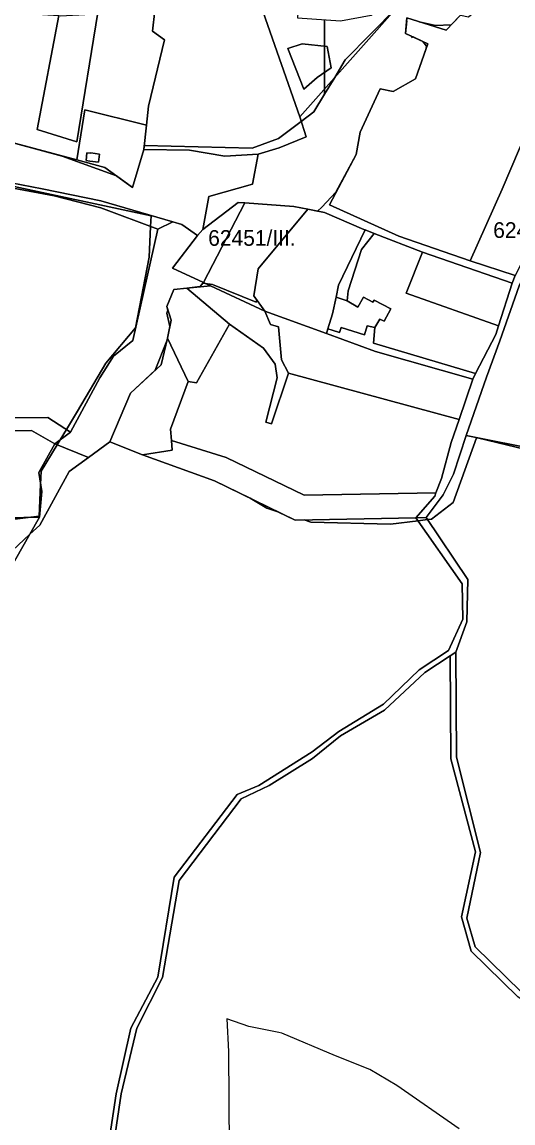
# Model space of a CAD drawing. Extents: x -502026 to -497664, y -1143484 to -1138019.
# Drawn here: x -498840 to -498590, y -1142180 to -1141619 of the extents above; entities that cross this region are included whole.
import ezdxf

# ---------------------------------------------------------------- set-up
doc = ezdxf.new("R2010")
doc.units = 0
for name, color, linetype in [('25', 7, 'Continuous'), ('31', 7, 'Continuous'), ('37', 7, 'Continuous'), ('43', 7, 'Continuous'), ('55', 7, 'Continuous'), ('62', 7, 'Continuous'), ('7', 7, 'Continuous')]:
    doc.layers.add(name, color=color, linetype=linetype)

msp = doc.modelspace()

# ---------------------------------------------------------------- linework, layer by layer
at = {"layer": '25'}
for points in [[(-498821.5, -1141615.93), (-498820.61, -1141616.01), (-498808.23, -1141615.35), (-498801.68, -1141614.26), (-498812.29, -1141680.22), (-498832.5, -1141673.92)], [(-498776.89, -1141671.76), (-498778.26, -1141684.08), (-498783.98, -1141703.56), (-498798.11, -1141693.25), (-498812.44, -1141689.43), (-498808.21, -1141663.92)], [(-498807.18, -1141685.78), (-498807.65, -1141689.81), (-498805.75, -1141690.03), (-498801.27, -1141690.56), (-498800.78, -1141686.44), (-498805.26, -1141685.9), (-498805.28, -1141686.01)], [(-498636.1, -1141736.52), (-498644.49, -1141757.44), (-498597.3, -1141774.04), (-498598.75, -1141778.37), (-498609.16, -1141798.36), (-498661.05, -1141782.91), (-498660.37, -1141774.86), (-498657.78, -1141770.53), (-498655.63, -1141771.68), (-498652.28, -1141765.42), (-498660.83, -1141760.84), (-498661.42, -1141761.94), (-498666.27, -1141759.35), (-498669.03, -1141764.51), (-498674.5, -1141761.18), (-498673.99, -1141756.14), (-498667.24, -1141735.13), (-498660.67, -1141726.97)], [(-498590.32, -1141752.32), (-498597.3, -1141774.04), (-498644.49, -1141757.44), (-498636.1, -1141736.52)]]:
    msp.add_lwpolyline(points, close=True, dxfattribs=at)
at = {"layer": '31'}
for points in [[(-498821.5, -1141615.93), (-498832.5, -1141673.92), (-498812.29, -1141680.22), (-498801.68, -1141614.26), (-498787.15, -1141613), (-498772.57, -1141613.25), (-498773.73, -1141623.84), (-498767.62, -1141628.33), (-498775.76, -1141662.06), (-498776.89, -1141671.76), (-498808.21, -1141663.92), (-498812.44, -1141689.43), (-498855.78, -1141677.89), (-498846.98, -1141615.47), (-498843.3, -1141602.91), (-498844.02, -1141614.47)], [(-498555.48, -1141734.78), (-498529.35, -1141741.87), (-498525.92, -1141742.8), (-498522.72, -1141754.01), (-498546.95, -1141790.01), (-498556.66, -1141818.24), (-498566.28, -1141830.25), (-498575.47, -1141837.59), (-498613.88, -1141829.95), (-498603.5, -1141800.08), (-498596.59, -1141781.61), (-498586.82, -1141753.62), (-498582.48, -1141744.58), (-498574.93, -1141729.51)]]:
    msp.add_lwpolyline(points, close=True, dxfattribs=at)
at = {"layer": '37'}
for points in [[(-498557.86, -1141620.31), (-498579.16, -1141667.75), (-498586.65, -1141683.62), (-498595.46, -1141704.28), (-498611.77, -1141740.81), (-498648.14, -1141728.24), (-498683.59, -1141712.28), (-498669.98, -1141686.66), (-498667.93, -1141675.26), (-498657.61, -1141653.21), (-498650.99, -1141654.52), (-498639.74, -1141648.11), (-498633.36, -1141630.35), (-498644.79, -1141624.98), (-498644.02, -1141617.12), (-498624.09, -1141623.37), (-498616.79, -1141615.76), (-498612.61, -1141616.54), (-498606.51, -1141611.58), (-498603.56, -1141602.08), (-498594.48, -1141602.56), (-498583.73, -1141606.31), (-498572.2, -1141605.96), (-498562.32, -1141613.57)], [(-498542.66, -1141654.6), (-498556.29, -1141686.3), (-498560.31, -1141693.56), (-498569.25, -1141709.41), (-498588.89, -1141748.42), (-498611.77, -1141740.81), (-498595.46, -1141704.28), (-498586.65, -1141683.62), (-498579.16, -1141667.75), (-498557.86, -1141620.31)], [(-498726.76, -1141711.34), (-498747.75, -1141751.96), (-498763.66, -1141744.65), (-498750.89, -1141728.01), (-498748.15, -1141724.96), (-498730.12, -1141711.09)], [(-498665.4, -1141725.13), (-498678.88, -1141753.3), (-498680.17, -1141759.36), (-498681.96, -1141767.81), (-498684.38, -1141775.59), (-498685.13, -1141777.99), (-498716.52, -1141766.51), (-498722.08, -1141758.73), (-498719.97, -1141744.88), (-498694.58, -1141714.57), (-498686.08, -1141716.19), (-498665.95, -1141724.92)], [(-498734.57, -1141773.1), (-498751.34, -1141803.01), (-498755.67, -1141802.36), (-498766.21, -1141780.37), (-498764.25, -1141771.04), (-498766.51, -1141764.17), (-498762.82, -1141755.42), (-498756.25, -1141754.78)], [(-498716.52, -1141766.51), (-498713.53, -1141773.24), (-498709.48, -1141774.43), (-498708.04, -1141791.33), (-498704.49, -1141798.18), (-498713.07, -1141823.97), (-498716.02, -1141823.16), (-498710.18, -1141800.46), (-498711.22, -1141793.46), (-498717.15, -1141785.3), (-498734.57, -1141773.1), (-498756.25, -1141754.78), (-498744.19, -1141753.6)], [(-498685.13, -1141777.99), (-498660.07, -1141787.08), (-498610.42, -1141801.16), (-498617.46, -1141821.72), (-498704.49, -1141798.18), (-498708.04, -1141791.33), (-498709.48, -1141774.43), (-498713.53, -1141773.24), (-498716.52, -1141766.51)], [(-498704.49, -1141798.18), (-498617.46, -1141821.72), (-498621.45, -1141833.38), (-498626.36, -1141851.84), (-498629.29, -1141859.04), (-498696.42, -1141860.25), (-498736.25, -1141841.02), (-498764.16, -1141832.39), (-498764.66, -1141826.73), (-498755.67, -1141802.36), (-498751.34, -1141803.01), (-498734.57, -1141773.1), (-498717.15, -1141785.3), (-498711.22, -1141793.46), (-498710.18, -1141800.46), (-498716.02, -1141823.16), (-498713.07, -1141823.97)], [(-498755.67, -1141802.36), (-498764.66, -1141826.73), (-498764.16, -1141832.39), (-498763.71, -1141837.32), (-498778.91, -1141839.71), (-498795.55, -1141833.14), (-498784.92, -1141808.33), (-498769.32, -1141793.86), (-498766.21, -1141780.37)], [(-498629.29, -1141859.04), (-498629.9, -1141860.75), (-498639.46, -1141871.81), (-498701.02, -1141873.04), (-498742.24, -1141853.01), (-498778.91, -1141839.71), (-498763.71, -1141837.32), (-498764.16, -1141832.39), (-498736.25, -1141841.02), (-498696.42, -1141860.25)]]:
    msp.add_lwpolyline(points, close=True, dxfattribs=at)
at = {"layer": '43'}
for points in [[(-498616.79, -1141615.76), (-498624.09, -1141623.37), (-498644.02, -1141617.12), (-498644.79, -1141624.98), (-498633.36, -1141630.35), (-498639.74, -1141648.11), (-498650.99, -1141654.52), (-498657.61, -1141653.21), (-498667.93, -1141675.26), (-498669.98, -1141686.66), (-498683.59, -1141712.28), (-498648.14, -1141728.24), (-498611.77, -1141740.81), (-498588.89, -1141748.42), (-498590.32, -1141752.32), (-498636.1, -1141736.52), (-498660.67, -1141726.97), (-498665.4, -1141725.13), (-498665.95, -1141724.92), (-498686.08, -1141716.19), (-498694.58, -1141714.57), (-498701.76, -1141713.2), (-498726.76, -1141711.34), (-498730.12, -1141711.09), (-498748.15, -1141724.96), (-498744.99, -1141708.14), (-498722.86, -1141701.75), (-498719.96, -1141686.46), (-498709.13, -1141683.37), (-498695.49, -1141677.7), (-498698.67, -1141667.49), (-498644.52, -1141606.48)], [(-498585.79, -1142113.33), (-498609.2, -1142090.53), (-498613.54, -1142075.78), (-498606.48, -1142042.32), (-498618.74, -1141993.74), (-498619.17, -1141940.28), (-498613.56, -1141924.87), (-498613.07, -1141903.28), (-498634.25, -1141871.68), (-498625.57, -1141860.09), (-498620.24, -1141849.65), (-498613.88, -1141829.95), (-498575.47, -1141837.59)], [(-498882.96, -1141961.82), (-498836.29, -1141880.09), (-498831.3, -1141875.54), (-498816.19, -1141848.16), (-498806.47, -1141841.09), (-498795.55, -1141833.14), (-498778.91, -1141839.71), (-498742.24, -1141853.01), (-498701.02, -1141873.04), (-498639.46, -1141871.81), (-498615.92, -1141905.51), (-498615.54, -1141923.48), (-498622.83, -1141939.42), (-498637.85, -1141949.33), (-498656.05, -1141966.79), (-498678.84, -1141980.67), (-498692.35, -1141991.08), (-498719.6, -1142008.18), (-498730.62, -1142012.89), (-498762.7, -1142055.02), (-498771, -1142105.96), (-498784.75, -1142131.98), (-498792.31, -1142165.39), (-498798.63, -1142207.03)], [(-498796.15, -1142208.64), (-498789.71, -1142165.39), (-498781.78, -1142131.86), (-498768.65, -1142106.08), (-498760.1, -1142056.63), (-498728.52, -1142015), (-498714.27, -1142008.3), (-498692.22, -1141994.42), (-498677.85, -1141983.02), (-498655.56, -1141969.89), (-498634.99, -1141950.68), (-498622.04, -1141942.16), (-498621.71, -1141994.61), (-498609.08, -1142042.07), (-498616.14, -1142075.16), (-498611.31, -1142092.76), (-498587.53, -1142115.93)], [(-498617.46, -1142183.22), (-498649.12, -1142161.15), (-498662.93, -1142153.06), (-498680.53, -1142146.01), (-498707.86, -1142134.5), (-498709.41, -1142134.19), (-498724.74, -1142131.13), (-498735.91, -1142127.17), (-498735.04, -1142143.75), (-498734.74, -1142193.6)]]:
    msp.add_lwpolyline(points, dxfattribs=at)
for points in [[(-498644.52, -1141606.48), (-498698.67, -1141667.49), (-498717.42, -1141614.15), (-498701.78, -1141614.38), (-498704.3, -1141604.77), (-498699.04, -1141604.63), (-498699.84, -1141617.04), (-498677.92, -1141618.49), (-498662.29, -1141615.75), (-498646.97, -1141605.13)], [(-498717.42, -1141614.15), (-498698.67, -1141667.49), (-498695.49, -1141677.7), (-498709.13, -1141683.37), (-498719.96, -1141686.46), (-498736.92, -1141687.62), (-498754.9, -1141684.48), (-498778.26, -1141684.08), (-498776.89, -1141671.76), (-498775.76, -1141662.06), (-498767.62, -1141628.33), (-498773.73, -1141623.84), (-498772.57, -1141613.25), (-498751.28, -1141613.52)], [(-498689.77, -1141647.51), (-498682.6, -1141642.51), (-498684.77, -1141631.71), (-498697.42, -1141630.34), (-498704.76, -1141632.68), (-498696.62, -1141653.32)], [(-498689.77, -1141647.51), (-498696.62, -1141653.32), (-498704.76, -1141632.68), (-498697.42, -1141630.34), (-498684.77, -1141631.71), (-498682.6, -1141642.51)], [(-498855.78, -1141677.89), (-498812.44, -1141689.43), (-498798.11, -1141693.25), (-498783.98, -1141703.56), (-498778.26, -1141684.08), (-498754.9, -1141684.48), (-498736.92, -1141687.62), (-498719.96, -1141686.46), (-498722.86, -1141701.75), (-498744.99, -1141708.14), (-498748.15, -1141724.96), (-498750.89, -1141728.01), (-498758.79, -1141722.34), (-498763.37, -1141720.97), (-498800.1, -1141710.36), (-498829.96, -1141704.16), (-498888.16, -1141692.96), (-498884.08, -1141657.97), (-498858.25, -1141677.23)], [(-498888.16, -1141692.96), (-498829.96, -1141704.16), (-498800.1, -1141710.36), (-498763.37, -1141720.97), (-498771.05, -1141724.78), (-498800.16, -1141713.8), (-498823.99, -1141707.76), (-498892.28, -1141695.09), (-498898.8, -1141749.89), (-498899.3, -1141749.74), (-498901.61, -1141749.05), (-498895.44, -1141691.56)], [(-498771.05, -1141724.78), (-498783.82, -1141781.52), (-498793.62, -1141789.4), (-498800.65, -1141800.45), (-498815.52, -1141828.19), (-498827.1, -1141820.71), (-498846.81, -1141820.95), (-498844.38, -1141766.25), (-498890.21, -1141752.47), (-498898.8, -1141749.89), (-498892.28, -1141695.09), (-498823.99, -1141707.76), (-498800.16, -1141713.8)], [(-498694.58, -1141714.57), (-498719.97, -1141744.88), (-498722.08, -1141758.73), (-498716.52, -1141766.51), (-498744.19, -1141753.6), (-498747.75, -1141751.96), (-498726.76, -1141711.34), (-498701.76, -1141713.2)], [(-498750.89, -1141728.01), (-498763.66, -1141744.65), (-498747.75, -1141751.96), (-498744.19, -1141753.6), (-498756.25, -1141754.78), (-498762.82, -1141755.42), (-498766.51, -1141764.17), (-498764.25, -1141771.04), (-498766.21, -1141780.37), (-498769.32, -1141793.86), (-498784.92, -1141808.33), (-498795.55, -1141833.14), (-498806.47, -1141841.09), (-498823.56, -1141834.14), (-498815.52, -1141828.19), (-498800.65, -1141800.45), (-498793.62, -1141789.4), (-498783.82, -1141781.52), (-498771.05, -1141724.78), (-498763.37, -1141720.97), (-498758.79, -1141722.34)], [(-498815.52, -1141828.19), (-498823.56, -1141834.14), (-498835.45, -1141827.39), (-498852.97, -1141827.71), (-498891.75, -1141835.55), (-498892.39, -1141825.03), (-498854.34, -1141821.04), (-498846.81, -1141820.95), (-498827.1, -1141820.71)], [(-498891.75, -1141835.55), (-498894.3, -1141879.79), (-498884.68, -1141890.79), (-498886.43, -1141906.85), (-498873.75, -1141912.84), (-498864.27, -1141913.69), (-498854.88, -1141882.87), (-498847.49, -1141871.9), (-498831.43, -1141871.58), (-498836.29, -1141880.09), (-498845.19, -1141888.54), (-498855.09, -1141910.58), (-498870.57, -1141928.09), (-498882.72, -1141924.83), (-498888.84, -1141912.29), (-498890.08, -1141893.23), (-498898.82, -1141880.4), (-498899.63, -1141849.7), (-498915.86, -1141836.03), (-498934.78, -1141833.99), (-498945.8, -1141832.8), (-498943.06, -1141828.91), (-498915.22, -1141832.49), (-498899.63, -1141845.2)], [(-498823.56, -1141834.14), (-498831.8, -1141848.82), (-498830.19, -1141858.46), (-498831.43, -1141871.58), (-498847.49, -1141871.9), (-498854.88, -1141882.87), (-498864.27, -1141913.69), (-498873.75, -1141912.84), (-498886.43, -1141906.85), (-498884.68, -1141890.79), (-498894.3, -1141879.79), (-498891.75, -1141835.55), (-498852.97, -1141827.71), (-498835.45, -1141827.39)], [(-498806.47, -1141841.09), (-498816.19, -1141848.16), (-498831.3, -1141875.54), (-498836.29, -1141880.09), (-498831.43, -1141871.58), (-498830.19, -1141858.46), (-498831.8, -1141848.82), (-498823.56, -1141834.14)], [(-498882.96, -1141961.82), (-498881.6, -1141927.22), (-498882.72, -1141924.83), (-498870.57, -1141928.09), (-498855.09, -1141910.58), (-498845.19, -1141888.54), (-498836.29, -1141880.09)], [(-498510.61, -1142245.56), (-498515.69, -1142244.53), (-498530.42, -1142218.91), (-498543.55, -1142186.32), (-498548.75, -1142159.68), (-498563.25, -1142133.53), (-498587.53, -1142115.93), (-498611.31, -1142092.76), (-498616.14, -1142075.16), (-498609.08, -1142042.07), (-498621.71, -1141994.61), (-498622.04, -1141942.16), (-498619.17, -1141940.28), (-498618.74, -1141993.74), (-498606.48, -1142042.32), (-498613.54, -1142075.78), (-498609.2, -1142090.53), (-498585.79, -1142113.33), (-498560.15, -1142133.78), (-498546.52, -1142157.94), (-498540.33, -1142185.7), (-498529.31, -1142214.45)]]:
    msp.add_lwpolyline(points, close=True, dxfattribs=at)
at = {"layer": '55'}
for points in [[(-498807.18, -1141685.78), (-498805.28, -1141686.01), (-498805.26, -1141685.9), (-498800.78, -1141686.44), (-498801.27, -1141690.56), (-498805.75, -1141690.03), (-498807.65, -1141689.81)], [(-498660.67, -1141726.97), (-498667.24, -1141735.13), (-498673.99, -1141756.14), (-498674.5, -1141761.18), (-498680.17, -1141759.36), (-498678.88, -1141753.3), (-498665.4, -1141725.13)], [(-498660.37, -1141774.86), (-498664.28, -1141774.06), (-498665.71, -1141778.63), (-498677.65, -1141774.88), (-498678.46, -1141777.45), (-498682.2, -1141776.27), (-498684.38, -1141775.59), (-498681.96, -1141767.81), (-498680.17, -1141759.36), (-498674.5, -1141761.18), (-498669.03, -1141764.51), (-498666.27, -1141759.35), (-498661.42, -1141761.94), (-498660.83, -1141760.84), (-498652.28, -1141765.42), (-498655.63, -1141771.68), (-498657.78, -1141770.53)]]:
    msp.add_lwpolyline(points, close=True, dxfattribs=at)
for points in [[(-498586.82, -1141753.62), (-498596.59, -1141781.61), (-498603.5, -1141800.08), (-498613.88, -1141829.95), (-498620.24, -1141849.65), (-498625.57, -1141860.09), (-498634.25, -1141871.68), (-498639.46, -1141871.81), (-498629.9, -1141860.75), (-498629.29, -1141859.04), (-498626.36, -1141851.84), (-498621.45, -1141833.38), (-498617.46, -1141821.72), (-498610.42, -1141801.16), (-498609.16, -1141798.36), (-498598.75, -1141778.37), (-498597.3, -1141774.04), (-498590.32, -1141752.32), (-498588.89, -1141748.42)], [(-498798.63, -1142207.03), (-498792.31, -1142165.39), (-498784.75, -1142131.98), (-498771, -1142105.96), (-498762.7, -1142055.02), (-498730.62, -1142012.89), (-498719.6, -1142008.18), (-498692.35, -1141991.08), (-498678.84, -1141980.67), (-498656.05, -1141966.79), (-498637.85, -1141949.33), (-498622.83, -1141939.42), (-498615.54, -1141923.48), (-498615.92, -1141905.51), (-498639.46, -1141871.81), (-498634.25, -1141871.68), (-498613.07, -1141903.28), (-498613.56, -1141924.87), (-498619.17, -1141940.28), (-498622.04, -1141942.16), (-498634.99, -1141950.68), (-498655.56, -1141969.89), (-498677.85, -1141983.02), (-498692.22, -1141994.42), (-498714.27, -1142008.3), (-498728.52, -1142015), (-498760.1, -1142056.63), (-498768.65, -1142106.08), (-498781.78, -1142131.86), (-498789.71, -1142165.39), (-498796.15, -1142208.64)]]:
    msp.add_lwpolyline(points, dxfattribs=at)
at = {"layer": '62'}
for points in [[(-498855.78, -1141677.89), (-498819.83, -1141687.46), (-498792.11, -1141697.62), (-498783.98, -1141703.56), (-498778.26, -1141684.08), (-498778.04, -1141682.06), (-498723, -1141683.5), (-498709.5, -1141678.5), (-498697.94, -1141669.83), (-498691.5, -1141665), (-498686, -1141656), (-498680.84, -1141647.4), (-498675.5, -1141638.5), (-498649.34, -1141611.92)], [(-498649.34, -1141611.92), (-498675.5, -1141638.5), (-498680.84, -1141647.4), (-498686, -1141656), (-498686, -1141653.21), (-498686, -1141644.88), (-498686, -1141631.58), (-498686, -1141617.95)], [(-498686, -1141617.95), (-498686, -1141631.58), (-498686, -1141644.88), (-498686, -1141653.21), (-498686, -1141656), (-498691.5, -1141665), (-498697.94, -1141669.83), (-498709.5, -1141678.5), (-498723, -1141683.5), (-498778.04, -1141682.06), (-498778.26, -1141684.08), (-498783.98, -1141703.56), (-498792.11, -1141697.62), (-498819.83, -1141687.46), (-498855.78, -1141677.89)], [(-498637.89, -1141619.04), (-498629.5, -1141621), (-498621.43, -1141620.6), (-498616.79, -1141615.76)], [(-498616.79, -1141615.76), (-498621.43, -1141620.6), (-498629.5, -1141621), (-498637.89, -1141619.04)], [(-498583.5, -1141837), (-498608.01, -1141831.12), (-498608.51, -1141831.02), (-498620.5, -1141864), (-498631.5, -1141872.5), (-498633.54, -1141872.74), (-498638.4, -1141873.32), (-498652.5, -1141875), (-498693, -1141874), (-498696.38, -1141872.95), (-498701.02, -1141873.04), (-498709.8, -1141868.77), (-498715.5, -1141867), (-498723.93, -1141861.91), (-498742.24, -1141853.01), (-498778.91, -1141839.71), (-498795.55, -1141833.14), (-498784.92, -1141808.33), (-498772.34, -1141796.66), (-498766.51, -1141781.66), (-498766.21, -1141780.37), (-498764.96, -1141774.42), (-498766.5, -1141767.5), (-498765.92, -1141765.96), (-498766.51, -1141764.17), (-498762.82, -1141755.42), (-498756.25, -1141754.78), (-498754.9, -1141754.65), (-498749.5, -1141754), (-498748.03, -1141752.18), (-498746.87, -1141752.36), (-498743.11, -1141752.96), (-498721, -1141762), (-498720.55, -1141760.87), (-498722.08, -1141758.73), (-498719.97, -1141744.88), (-498694.58, -1141714.57), (-498689.58, -1141715.52), (-498687.5, -1141713.5), (-498680.22, -1141705.94), (-498669.98, -1141686.66), (-498667.93, -1141675.26), (-498657.61, -1141653.21), (-498650.99, -1141654.52), (-498639.74, -1141648.11), (-498634.17, -1141632.6), (-498634, -1141631.5), (-498635.93, -1141629.14), (-498640.91, -1141626.8), (-498641.5, -1141627), (-498641.68, -1141626.44), (-498644.79, -1141624.98), (-498644.16, -1141618.57)], [(-498644.16, -1141618.57), (-498644.79, -1141624.98), (-498641.68, -1141626.44), (-498641.5, -1141627), (-498640.91, -1141626.8), (-498635.93, -1141629.14), (-498634, -1141631.5), (-498634.17, -1141632.6), (-498639.74, -1141648.11), (-498650.99, -1141654.52), (-498657.61, -1141653.21), (-498667.93, -1141675.26), (-498669.98, -1141686.66), (-498680.22, -1141705.94), (-498687.5, -1141713.5), (-498689.58, -1141715.52), (-498694.58, -1141714.57), (-498719.97, -1141744.88), (-498722.08, -1141758.73), (-498720.55, -1141760.87), (-498721, -1141762), (-498743.11, -1141752.96), (-498746.87, -1141752.36), (-498748.03, -1141752.18), (-498749.5, -1141754), (-498754.9, -1141754.65), (-498756.25, -1141754.78), (-498762.82, -1141755.42), (-498766.51, -1141764.17), (-498765.92, -1141765.96), (-498766.5, -1141767.5), (-498764.96, -1141774.42), (-498766.21, -1141780.37), (-498766.51, -1141781.66), (-498772.34, -1141796.66), (-498784.92, -1141808.33), (-498795.55, -1141833.14), (-498778.91, -1141839.71), (-498742.24, -1141853.01), (-498723.93, -1141861.91), (-498715.5, -1141867), (-498709.8, -1141868.77), (-498701.02, -1141873.04), (-498696.38, -1141872.95), (-498693, -1141874), (-498652.5, -1141875), (-498638.4, -1141873.32), (-498633.54, -1141872.74), (-498631.5, -1141872.5), (-498620.5, -1141864), (-498608.51, -1141831.02), (-498608.01, -1141831.12), (-498583.5, -1141837)], [(-498851.5, -1141701.5), (-498774.5, -1141718), (-498774.76, -1141723.38), (-498775.5, -1141739), (-498782.5, -1141775), (-498797.5, -1141793), (-498812, -1141817.5), (-498817.65, -1141826.81), (-498820.9, -1141832.17), (-498822.38, -1141834.62), (-498830.5, -1141848), (-498830.8, -1141854.83), (-498831.5, -1141871), (-498837.24, -1141871.69), (-498848, -1141873)], [(-498848, -1141873), (-498837.24, -1141871.69), (-498831.5, -1141871), (-498830.8, -1141854.83), (-498830.5, -1141848), (-498822.38, -1141834.62), (-498820.9, -1141832.17), (-498817.65, -1141826.81), (-498812, -1141817.5), (-498797.5, -1141793), (-498782.5, -1141775), (-498775.5, -1141739), (-498774.76, -1141723.38), (-498774.5, -1141718), (-498851.5, -1141701.5)], [(-498617.46, -1142183.22), (-498649.12, -1142161.15), (-498662.93, -1142153.06), (-498680.53, -1142146.01), (-498707.86, -1142134.5), (-498709.41, -1142134.19), (-498724.74, -1142131.13), (-498735.91, -1142127.17), (-498735.04, -1142143.75), (-498734.74, -1142193.6)]]:
    msp.add_lwpolyline(points, dxfattribs=at)
for points in [[(-498726.76, -1141711.34), (-498747.75, -1141751.96), (-498763.66, -1141744.65), (-498750.89, -1141728.01), (-498748.15, -1141724.96), (-498730.12, -1141711.09)], [(-498726.76, -1141711.34), (-498730.12, -1141711.09), (-498748.15, -1141724.96), (-498750.89, -1141728.01), (-498763.66, -1141744.65), (-498747.75, -1141751.96)]]:
    msp.add_lwpolyline(points, close=True, dxfattribs=at)
at = {"layer": '7'}
msp.add_lwpolyline([(-498660.37, -1141774.86), (-498661.05, -1141782.91), (-498609.16, -1141798.36), (-498610.42, -1141801.16), (-498660.07, -1141787.08), (-498685.13, -1141777.99), (-498684.38, -1141775.59), (-498682.2, -1141776.27), (-498678.46, -1141777.45), (-498677.65, -1141774.88), (-498665.71, -1141778.63), (-498664.28, -1141774.06)], close=True, dxfattribs=at)

# ---------------------------------------------------------------- texts
at = {"layer": '62'}
for p in [(-498745.38, -1141733.22), (-498600.05, -1141729.21)]:
    msp.add_text('62451/III.', height=8, dxfattribs=at).set_placement(p)

doc.saveas('drawing.dxf')
